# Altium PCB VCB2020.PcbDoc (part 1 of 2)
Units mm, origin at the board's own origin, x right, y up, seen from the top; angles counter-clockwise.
Board outline 146 x 101 mm, 2 copper layers (Top Layer, Bottom Layer); 144 components, 94 nets, 477 pads, 404 vias.
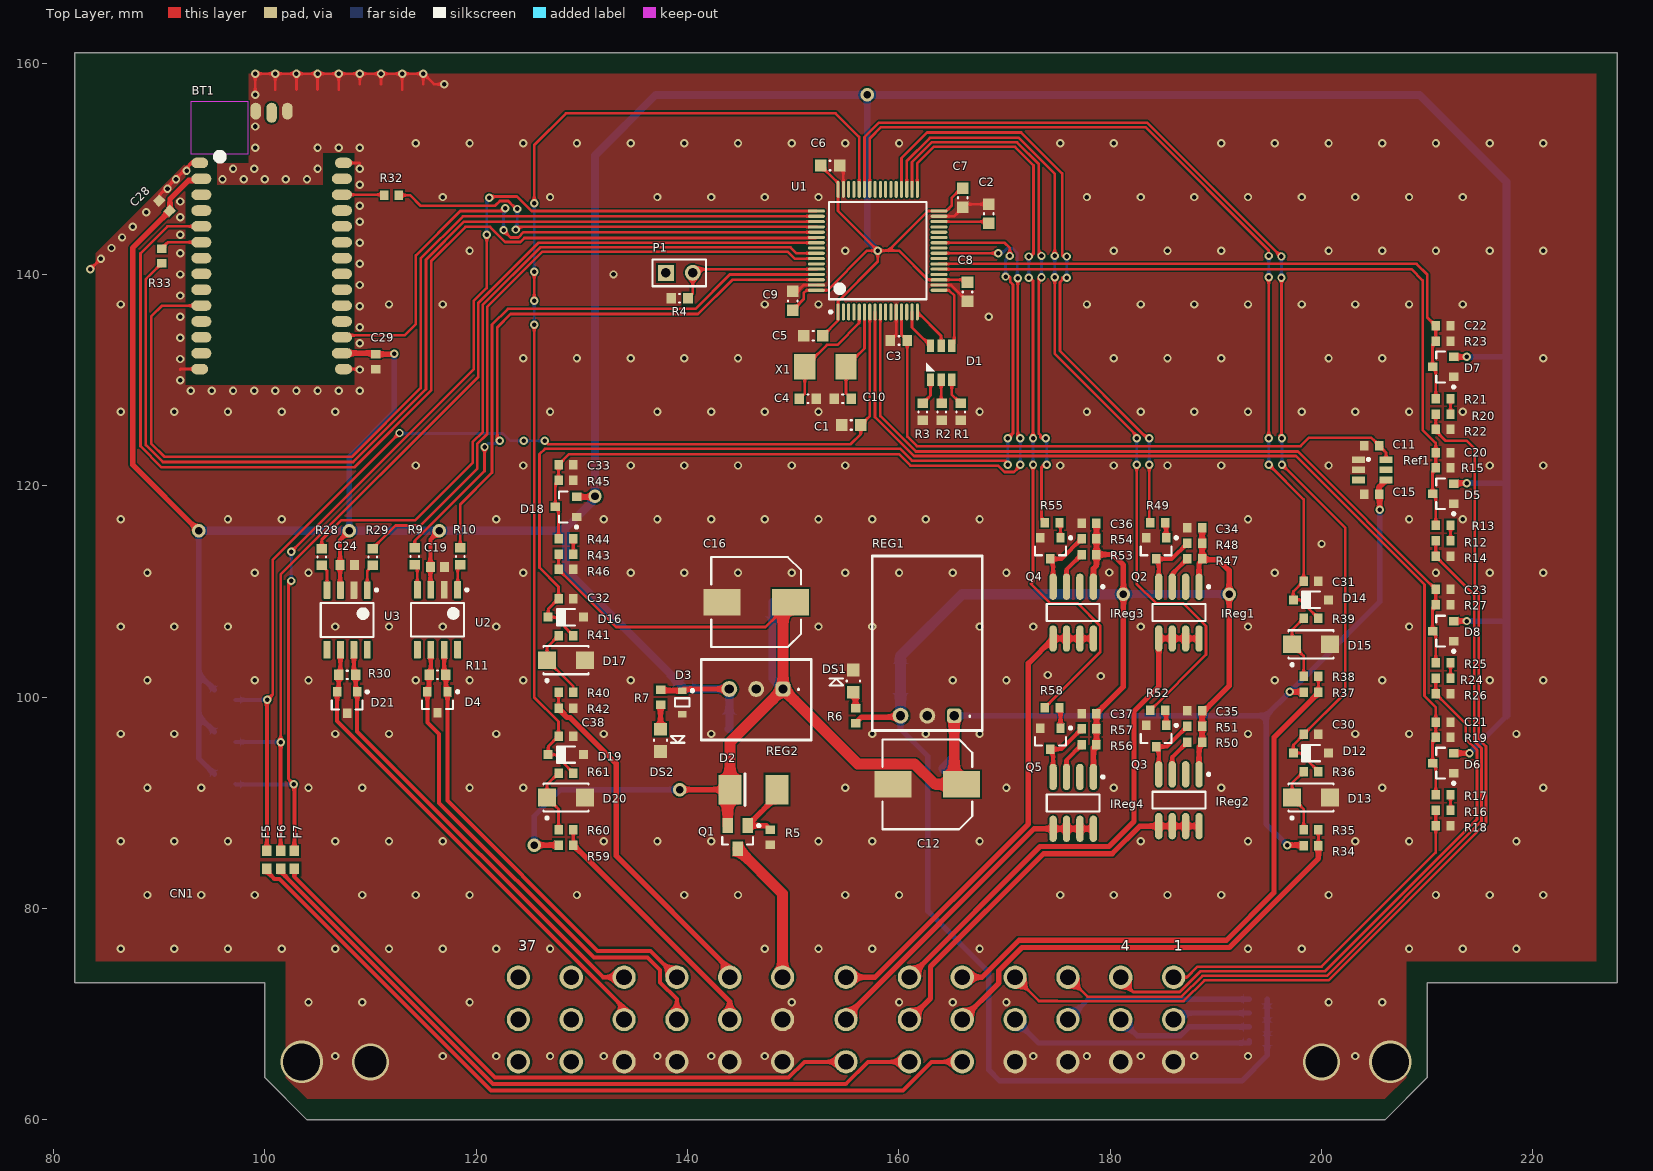
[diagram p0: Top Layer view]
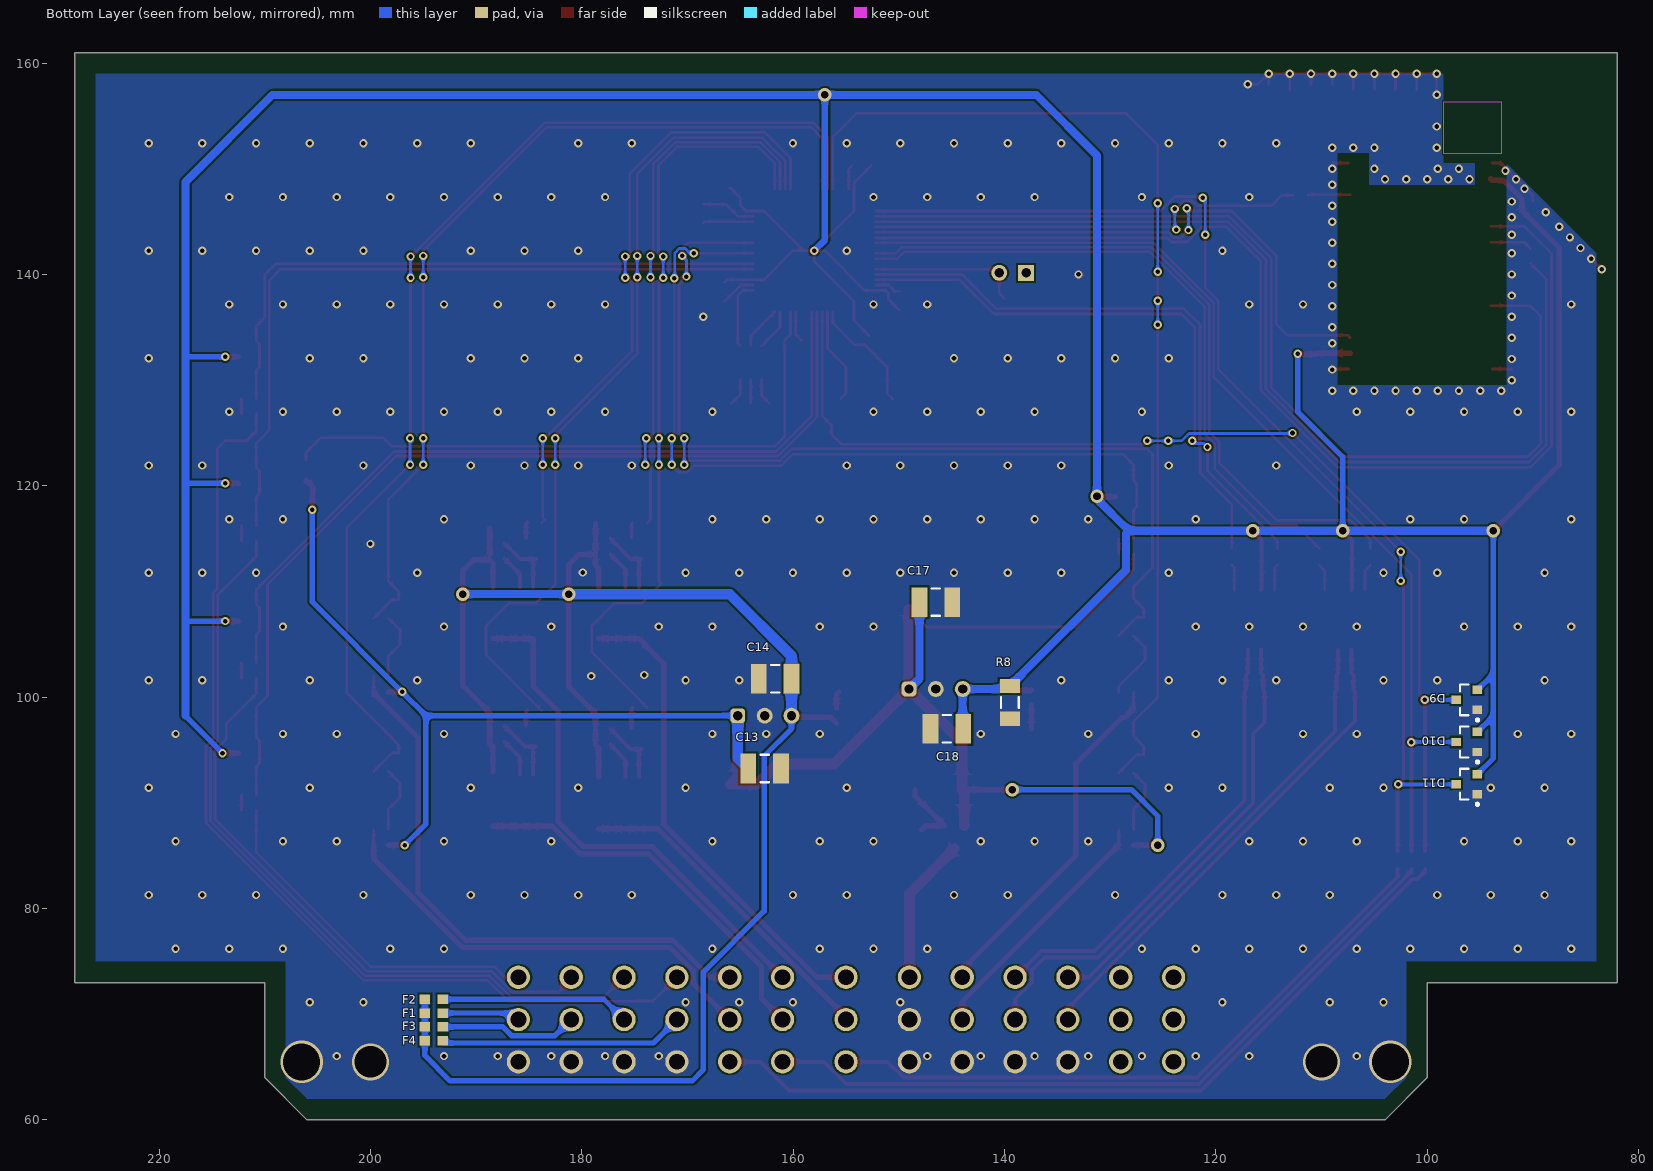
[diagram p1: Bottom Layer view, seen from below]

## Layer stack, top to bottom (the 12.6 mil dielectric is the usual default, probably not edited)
Top Solder: solder mask 0.0102, Solder Resist, Dk 3.5
Top Layer: signal copper 0.0356
Dielectric 1: dielectric 0.32, FR-4, Dk 4.8
Bottom Layer: signal copper 0.0356
Bottom Solder: solder mask 0.0102, Solder Resist, Dk 3.5

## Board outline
210,64 206,60 104,60 100,64 100,73 82,73 82,161 228,161 228,73 210,73

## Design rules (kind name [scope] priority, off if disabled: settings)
Clearance [All] p1: gap=0.178 ignorepadtopadclearanceinfootprint=FALSE except(0: Arc-Hole Track-Hole SMDPad-Hole THPad-Hole Via-Hole Fill-Hole Poly-Hole Region-Hole Text-Hole)
DiffPairsRouting [All] p1: maxlimit=0.254 minlimit=0.254 mostfreqgap=0.254 toplayer_minwidth=0.381 toplayer_maxwidth=0.381 toplayer_prefwidth=0.381 bottomlayer_minwidth=0.381 bottomlayer_maxwidth=0.381 bottomlayer_prefwidth=0.381 maxuncoupledlength=12.7
Height [All] p1: minheight=0 maxheight=1000 prefheight=12.7
HoleSize [All] p1: absolutevalues=TRUE maxlimit=5.08 minlimit=0.381 maxpercent=80.000 minpercent=20.000
HoleToHoleClearance [All] p1: gap=0.203 allowstackedmicrovias=TRUE
MinimumAnnularRing MinimumAnnularRing_Pad [IsPad] p1: minimumring=0.178
MinimumAnnularRing MinimumAnnularRing_Via [IsVia] p2: minimumring=0.127
MinimumSolderMaskSliver [All] p1: minsoldermaskwidth=0.102
PlaneClearance [All] p1: clearance=0.381
PlaneConnect PlaneConnect_12V [InNet('12V')] p1: planeconnectstyle=Direct reliefexpansion=0.508 reliefentries=4 reliefconductorwidth=0.508 reliefairgap=0.254
PlaneConnect PlaneConnect_1 [All] p2: planeconnectstyle=Relief reliefexpansion=0.381 reliefentries=4 reliefconductorwidth=0.381 reliefairgap=0.254
PolygonConnect [All] p1: connectstyle=Direct reliefconductorwidth=0.381 reliefentries=4 polygonreliefangle="90 Angle" airgapwidth=0.254
RoutingVias [All] p1: holewidth=0.432 width=0.787 viastyle="Through Hole" minholewidth=0.381 minwidth=0.737 maxholewidth=1.27 maxwidth=2.54
SilkToSilkClearance [All] p1: silktosilkclearance=0.178
SilkToSolderMaskClearance [IsPad] p1: minsilkscreentomaskgap=0.051 clearancetoexposedcopper=TRUE
SolderMaskExpansion [All] p1: expansion=0.076
Width [All] p1: maxlimit=5.08 minlimit=0.178 preferedwidth=0.381
21 further rules are at their usual default settings.

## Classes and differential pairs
component class 10-DashLEDs: C34 C35 C36 C37 IReg1 IReg2 IReg3 IReg4 Q2 Q3 Q4 Q5 R47 R48 R49 R50 R51 R52 R53 R54 R55 R56 R57 R58
component class 9-Other_Inputs: C30 C31 C32 C33 C38 D12 D13 D14 D15 D16 D17 D18 D19 D20 R34 R35 R36 R37 R38 R39 R40 R41 R42 R43 R44 R45 R46 R59 R60 R61
component class 8-Bluetooth: BT1 C28 C29 R32 R33
component class 5-Connector: CN1 D9 D10 D11 F1 F2 F3 F4 F5 F6 F7
component class 4-PPS: C20 C21 C22 C23 D5 D6 D7 D8 R12 R13 R14 R15 R16 R17 R18 R19 R20 R21 R22 R23 R24 R25 R26 R27
component class 3-CAN: C19 C24 D4 D21 R9 R10 R11 R28 R29 R30 U2 U3
component class 2-Power: C11 C12 C13 C14 C15 C16 C17 C18 D2 D3 DS1 DS2 Q1 R5 R6 R7 R8 Ref1 REG1 REG2
component class 1-Controller: C1 C2 C3 C4 C5 C6 C7 C8 C9 C10 D1 P1 R1 R2 R3 R4 U1 X1
differential pair Sensor_CAN: +Sensor_CAN_P -Sensor_CAN_N
differential pair CAN: +CAN_P -CAN_N

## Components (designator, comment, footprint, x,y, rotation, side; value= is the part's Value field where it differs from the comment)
BT1 "WT12" WT12 100.65,147.95 r270 top
C1 "CAP 10nF 100V 0603(1608)" CAPC0603(1608)100_M 155.5,125.75 r0 top value=10nF
C2 "CAP 4.7uF 10V 0603" CAPC0603(1608)100_M 168.5,145.75 r270 top value=4.7uF
C3 "CAP 100nF 25V 0603(1608)" CAPC0603(1608)100_N 160,133.75 r0 top value=100nF
C4 "CAP 24pF" CAPC0603(1608)100_N 151.396,128.25 r180 top value=24pF
C5 "CAP 10nF 100V 0603(1608)" CAPC0603(1608)100_M 151.9,134.196 r0 top value=10nF
C6 "CAP 10nF 100V 0603(1608)" CAPC0603(1608)100_M 153.5,150.304 r180 top value=10nF
C7 "CAP 10nF 100V 0603(1608)" CAPC0603(1608)100_M 166.054,147.25 r90 top value=10nF
C8 "CAP 10nF 100V 0603(1608)" CAPC0603(1608)100_M 166.5,138.35 r90 top value=10nF
C9 "CAP 10nF 100V 0603(1608)" CAPC0603(1608)100_M 149.946,137.5 r270 top value=10nF
C10 "CAP 24pF" CAPC0603(1608)100_N 154.7,128.25 r0 top value=24pF
C11 "Cap" 1608[0603] 204.75,123.804 r0 top value=1uF
C12 "UUD1H101MNL1GS" NIC-CAPA2-8X10_V 162.7,91.75 r180 top
C13 "Cap" C1210_M 162.7,93.25 r0 bottom value=22uF
C14 "Cap" C1210_M 161.7,101.75 r180 bottom value=10uF
C15 "Cap" 1608[0603] 204.75,119.196 r0 top value=100nF
C16 "UUD1H101MNL1GS" NIC-CAPA2-8X10_V 146.5,109 r180 top
C17 "Cap" C1210_M 146.5,109 r0 bottom value=22uF
C18 "Cap" C1210_M 145.45,97 r180 bottom value=10uF
C19 "0.1uF" CAPC1608X90X30NL10T20 116.345,112.329 r180 top
C20 "Cap" 1608[0603] 211.5,123.144 r180 top value=0.47uF
C21 "Cap" 1608[0603] 211.5,97.644 r180 top value=0.47uF
C22 "Cap" 1608[0603] 211.5,135.144 r180 top value=0.47uF
C23 "Cap" 1608[0603] 211.5,110.204 r180 top value=0.47uF
C24 "0.1uF" CAPC1608X90X30NL10T20 107.8,112.513 r180 top
C28 "Cap" 1608[0603] 90.5,146.5 r315 top value=100nF
C29 "Cap" 1608[0603] 110.5,131.75 r90 top value=100nF
C30 "Cap" 1608[0603] 199,96.471 r180 top value=100nF
C31 "Cap" 1608[0603] 199,110.971 r180 top value=100nF
C32 "Cap" 1608[0603] 128.5,109.321 r180 top value=1nF
C33 "Cap" 1608[0603] 128.5,121.996 r180 top value=0.47uF
C34 "Cap" 1608[0603] 188,116.013 r0 top value=100nF
C35 "Cap" 1608[0603] 188,98.704 r0 top value=100nF
C36 "Cap" 1608[0603] 178,116.454 r0 top value=100nF
C37 "Cap" 1608[0603] 178,98.454 r0 top value=100nF
C38 "Cap" 1608[0603] 128.5,96.321 r180 top value=100nF
CN1 "5-1418363-3" 5-1418363-3 155,69.5 r0 top
D1 "CLX6F-FKC-CNP1ST1E1BB7D3D3" CLX6C-FKB 164,130.05 r90 top
D2 "Zener Diode, 5.1V, 5W SMBJ5338B" "DO-214AA (SMB)" 146.25,91.25 r180 top
D3 "MM3Z3V6T1G" ONSC-SOD-323-2-477-02_V 139.5,99.5 r270 top
D4 "NUP2105LT1" ONSC-SOT-23-3-318-08_V 116.345,99.516 r270 top
D5 "SZNUP1301ML3T1G" ONSC-SOT-23-3-318-08_V 211.5,119.25 r180 top
D6 "SZNUP1301ML3T1G" ONSC-SOT-23-3-318-08_V 211.5,93.75 r180 top
D7 "SZNUP1301ML3T1G" ONSC-SOT-23-3-318-08_V 211.5,131.25 r180 top
D8 "SZNUP1301ML3T1G" ONSC-SOT-23-3-318-08_V 211.5,106.25 r180 top
D9 "SZNUP1301ML3T1G" ONSC-SOT-23-3-318-08_V 96.25,99.75 r0 bottom
D10 "SZNUP1301ML3T1G" ONSC-SOT-23-3-318-08_V 96.25,95.761 r0 bottom
D11 "SZNUP1301ML3T1G" ONSC-SOT-23-3-318-08_V 96.25,91.771 r0 bottom
D12 "MMSZ5226B-E3-08" VISH-SOD-123-2_V 199,94.717 r180 top
D13 "SS14-E3/5AT" VISH-DO-214AC-2_V 199,90.5 r180 top
D14 "MMSZ5226B-E3-08" VISH-SOD-123-2_V 199,109.217 r180 top
D15 "SS14-E3/5AT" VISH-DO-214AC-2_V 199,105 r180 top
D16 "MMSZ5226B-E3-08" VISH-SOD-123-2_V 128.5,107.567 r180 top
D17 "SS14-E3/5AT" VISH-DO-214AC-2_V 128.5,103.5 r180 top
D18 "SZNUP1301ML3T1G" ONSC-SOT-23-3-318-08_V 128.5,118 r180 top
D19 "MMSZ5226B-E3-08" VISH-SOD-123-2_V 128.5,94.567 r180 top
D20 "SS14-E3/5AT" VISH-DO-214AC-2_V 128.5,90.5 r180 top
D21 "NUP2105LT1" ONSC-SOT-23-3-318-08_V 107.8,99.5 r270 top
DS1 "LTST-C170GKT" LTST-C170GKT_V 155.7,101.529 r90 top
DS2 "LTST-C170GKT" LTST-C170GKT_V 137.45,95.916 r270 top
F1 "PTC 80 mA" "0603 fuse" 194,70.113 r180 bottom
F2 "PTC 80 mA" "0603 fuse" 194,71.42 r180 bottom
F3 "PTC 80 mA" "0603 fuse" 194,68.807 r180 bottom
F4 "PTC 80 mA" "0603 fuse" 194,67.5 r180 bottom
F5 "PTC 80 mA" "0603 fuse" 100.193,84.6 r270 top
F6 "PTC 80 mA" "0603 fuse" 101.5,84.6 r270 top
F7 "PTC 80 mA" "0603 fuse" 102.807,84.6 r270 top
IReg1 "NUD4001" SO8_M 186.5,108 r270 top
IReg2 "NUD4001" SO8_M 186.5,90.25 r270 top
IReg3 "NUD4001" SO8_M 176.5,108 r270 top
IReg4 "NUD4001" SO8_M 176.5,90 r270 top
P1 "Header 2" HDR1X2 137.96,140.149 r0 top
Q1 "FDN340P" FAIR-SSOT3L-3_V 144.75,86.75 r270 top
Q2 "MMBT2222ALT1" ONSC-SOT-23-3-318-08_V 184.346,114.079 r270 top
Q3 "MMBT2222ALT1" ONSC-SOT-23-3-318-08_V 184.346,96.329 r270 top
Q4 "MMBT2222ALT1" ONSC-SOT-23-3-318-08_V 174.346,114.079 r270 top
Q5 "MMBT2222ALT1" ONSC-SOT-23-3-318-08_V 174.346,96.079 r270 top
R1 "82R" RESC0603(1608)_N 165.859,127 r270 top value="82.00 Ohm"
R2 "60R" RESC0603(1608)_N 164.054,127 r270 top value="60.40 Ohm"
R3 "33R" RESC0603(1608)_N 162.25,127 r270 top value="33.00 Ohm"
R4 "10K" RESC0603(1608)_N 139.25,137.75 r180 top value="10000.00 Ohm"
R5 "Res1" 1608[0603] 147.854,86.75 r90 top value=1K
R6 "Res1" 1608[0603] 155.904,98.25 r90 top value=180R
R7 "Res1" 1608[0603] 137.45,100 r270 top value=82R
R8 "100R" RESC1206(3216)_M 139.5,99.5 r90 bottom value="100.00 Ohm"
R9 "22R" RESC0603(1608)_N 114.191,113.321 r90 top value="22.00 Ohm"
R10 "22R" RESC0603(1608)_N 118.499,113.321 r90 top value="22.00 Ohm"
R11 "120R" RESC0603(1608)_N 116.345,102.121 r0 top value="120.00 Ohm"
R12 "Res1" 1608[0603] 211.5,114.791 r0 top value=3k9
R13 "Res1" 1608[0603] 211.5,116.246 r180 top value=1k3
R14 "Res1" 1608[0603] 211.5,113.337 r180 top value=10k
R15 "Res1" 1608[0603] 211.5,121.689 r180 top value=10k
R16 "Res1" 1608[0603] 211.5,89.291 r0 top value=3k9
R17 "Res1" 1608[0603] 211.5,90.746 r180 top value=1k3
R18 "Res1" 1608[0603] 211.5,87.837 r180 top value=10k
R19 "Res1" 1608[0603] 211.5,96.189 r180 top value=10k
R20 "Res1" 1608[0603] 211.5,126.791 r0 top value=3k9
R21 "Res1" 1608[0603] 211.5,128.246 r180 top value=1k3
R22 "Res1" 1608[0603] 211.5,125.337 r180 top value=10k
R23 "Res1" 1608[0603] 211.5,133.689 r180 top value=10k
R24 "Res1" 1608[0603] 211.5,101.791 r0 top value=3k9
R25 "Res1" 1608[0603] 211.5,103.246 r180 top value=1k3
R26 "Res1" 1608[0603] 211.5,100.337 r180 top value=10k
R27 "Res1" 1608[0603] 211.5,108.75 r180 top value=10k
R28 "22R" RESC0603(1608)_N 105.396,113.263 r90 top value="22.00 Ohm"
R29 "22R" RESC0603(1608)_N 110.204,113.263 r90 top value="22.00 Ohm"
R30 "120R" RESC0603(1608)_N 107.8,102.104 r0 top value="120.00 Ohm"
R32 "Res1" 1608[0603] 112,147.5 r0 top value=22R
R33 "Res1" 1608[0603] 90.25,141.75 r90 top value=22R
R34 "Res1" 1608[0603] 199,85.963 r180 top value=10k
R35 "Res1" 1608[0603] 199,87.463 r180 top value=5k1
R36 "Res1" 1608[0603] 199,92.963 r0 top value=5k1
R37 "Res1" 1608[0603] 199,100.463 r180 top value=10k
R38 "Res1" 1608[0603] 199,101.963 r180 top value=5k1
R39 "Res1" 1608[0603] 199,107.463 r0 top value=5k1
R40 "Res1" 1608[0603] 128.5,100.463 r180 top value=1K
R41 "Res1" 1608[0603] 128.5,105.812 r180 top value=1K
R42 "Res1" 1608[0603] 128.5,98.963 r180 top value=1K
R43 "Res1" 1608[0603] 128.5,113.541 r0 top value=39k
R44 "Res1" 1608[0603] 128.5,114.996 r180 top value=2k
R45 "Res1" 1608[0603] 128.5,120.541 r180 top value=10k
R46 "Res1" 1608[0603] 128.5,112.087 r180 top value=10k
R47 "Res1" 1608[0603] 188,113.104 r180 top value=3R
R48 "Res1" 1608[0603] 188,114.559 r180 top value=110k
R49 "Res1" 1608[0603] 184.5,116.509 r180 top value=1K
R50 "Res1" 1608[0603] 188,95.75 r180 top value=3R
R51 "Res1" 1608[0603] 188,97.25 r180 top value=110k
R52 "Res1" 1608[0603] 184.5,98.759 r180 top value=1K
R53 "Res1" 1608[0603] 178,113.5 r180 top value=3R
R54 "Res1" 1608[0603] 178,115 r180 top value=110k
R55 "Res1" 1608[0603] 174.5,116.509 r180 top value=1K
R56 "Res1" 1608[0603] 178,95.5 r180 top value=3R
R57 "Res1" 1608[0603] 178,97 r180 top value=110k
R58 "Res1" 1608[0603] 174.5,99 r180 top value=1K
R59 "Res1" 1608[0603] 128.5,86.008 r180 top value=10k
R60 "Res1" 1608[0603] 128.5,87.463 r180 top value=5k1
R61 "Res1" 1608[0603] 128.5,92.812 r0 top value=5k1
Ref1 "LT6654AHS6-3.3" "TSOT-23 S6" 204.75,121.5 r0 top
REG1 "OKI-78SR-5" "Reg - TH, 3 pin, 100 mil Pitch, HTL" 162.7,96.98 r180 top
REG2 "OKI-78SR-3.3" "Reg - TH, 3 pin, 100 mil Pitch, VTL" 146.5,99.5 r180 top
U1 "STM32F446RCT7TR" STM-LQFP64_L 158,142.25 r90 top
U2 "SN65HVD232DR" D0008A_M 116.345,107.325 r270 top
U3 "SN65HVD232DR" D0008A_M 107.8,107.309 r270 top
X1 "7A-8.000MAAJ-T" "2-SMD, No Lead" 153,131.25 r180 top

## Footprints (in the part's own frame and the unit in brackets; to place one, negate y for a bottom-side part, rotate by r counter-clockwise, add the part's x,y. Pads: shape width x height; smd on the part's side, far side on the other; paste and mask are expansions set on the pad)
"2-SMD, No Lead" [mm]
  rect 2x2.4 smd: 1(-2,0) 2(1.9,0)
  body extent -2.5,-1.6 2.5,1.6, height 1.2
5-1418363-3 [mm] "Levyseal 90 degree 39 pin header"
  round 2.2 hole 1.5: 1(31,4) 2(31,0) 3(31,-4) 4(26,4) 5(26,0) 6(26,-4) 7(21,4) 8(21,0) 9(21,-4) 10(16,4) 11(16,0) 12(16,-4) 13(11,4) 14(11,0) 15(11,-4) 16(6,4) 17(6,0) 18(6,-4) 19(0,4) 20(0,0) 21(0,-4) 22(-6,4) 23(-6,0) 24(-6,-4) 25(-11,4) 26(-11,0) 27(-11,-4) 28(-16,4) 29(-16,0) 30(-16,-4) 31(-21,4) 32(-21,0) 33(-21,-4) 34(-26,4) 35(-26,0) 36(-26,-4) 37(-31,4) 38(-31,0) 39(-31,-4)
  body extent -66,-47.4 66,10.4, height 37
"0603 fuse" [mm] "0603 PTC fuse"
  rect 1x0.9 smd: 1(-0.85,0) 2(0.85,0)
  body extent -1,-0.41 1,0.41, height 0.7
1608[0603] [mm] "Chip Capacitor, Body 1.6x0.8mm, IPC High Density"
  rect 0.8x0.9 smd: 1(-0.7,0) 2(0.7,0)
  body extent -0.87,-0.48 0.87,0.48, height 1.3
C1210_M [mm] "Chip Capacitor, Body 3.2x2.5mm, IPC Low Density"
  rect 1.5x2.8 smd: 1(-1.55,0) 2(1.55,0)
  silkscreen extent -0.4,-1.3 0.4,1.3, body extent -1.7,-1.35 1.7,1.35, height 1.5
CAPC0603(1608)100_M [mm] "Chip Capacitor, Body 1.6x0.8mm, Height 1.0mm, IPC Low Density"
  rect 1.1x1.1 smd: 1(-0.9,0) 2(0.9,0)
  silkscreen extent -0.05,-0.45 0.05,0.45, body extent -0.87,-0.47 0.88,0.48, height 1
CAPC0603(1608)100_N [mm] "Chip Capacitor, Body 1.6x0.8mm, Height 1.0mm, IPC Medium Density"
  rect 0.9x1 smd: 1(-0.8,0) 2(0.8,0)
  silkscreen extent -0.05,-0.4 0.05,0.4, body extent -0.87,-0.48 0.88,0.47, height 1
CAPC1608X90X30NL10T20 [mm] "Chip Capacitor, 2-Leads, Body 1.70x0.90mm, IPC Medium Density"
  rect 0.85x0.95 smd: 1(-0.675,0) 2(0.675,0)
  body extent -0.85,-0.45 0.85,0.45, height 0.9
CLX6C-FKB [mm] "6-SMD, J-Lead, 1mm"
  rect 1.2x0.7 smd: 1(0,1) 2(0,0) 3(0,-1) 4(3.2,-1) 5(3.2,0) 6(3.2,1)
  silkscreen extent 0.8,0.6 1.6,1.4, body extent -0.1,-1.7 3.3,1.7, height 1
D0008A_M [mm] "SOIC, 8-Leads, Body 5x4mm, Pitch 1.27mm, IPC Low Density"
  rrect15% 1.65x0.65 smd: 1(-2.825,1.905) 2(-2.825,0.635) 3(-2.825,-0.635) 4(-2.825,-1.905) 5(2.825,-1.905) 6(2.825,-0.635) 7(2.825,0.635) 8(2.825,1.905)
  silkscreen extent -2.95,-2.5 1.6,2.91, body extent -3,-2.45 3,2.45, height 1.63
"DO-214AA (SMB)" [mm]
  rect 2.16x2.8 smd: A(-2.225,0) K(2.225,0)
  silkscreen extent 0.8,-1.5 0.8,1.5, body extent -2.87,-1.95 2.88,1.95, height 2.41
FAIR-SSOT3L-3_V [mm] "SOT23, 3-Leads, Body 2.92x1.4mm, Pitch 0.95mm"
  rect 1.4x1 smd: 1(-1.1,0.95) 2(-1.1,-0.95) 3(1.1,0)
  silkscreen extent -1.22,-1.46 0.7,2.13, body extent -1.26,-1.46 1.26,1.46, height 1.12
HDR1X2 [mm] "Connector; Header; 2 Position"
  rect 1.5x1.5 hole 0.9: 1(0,0)
  round 1.5 hole 0.9: 2(2.54,0)
  silkscreen extent -1.27,-1.27 3.81,1.27
LTST-C170GKT_V [mm] "SMD, 2-Leads, Body 2x1.25mm"
  rect 1.2x1.2 smd: 1(-1.05,0) 2(1.05,0)
  silkscreen extent -0.41,-0.63 0.23,2.25, body extent -1,-0.63 1,0.63, height 1.1
NIC-CAPA2-8X10_V [mm] "Aluminum Electrolytic Capacitor, Diameter 8mm, Height 10.8mm, Pitch 6.5mm"
  rect 3.5x2.5 smd: 1(-3.25,0) 2(3.25,0)
  silkscreen extent -4.25,-4.25 4.25,4.25, body extent -3.99,-3.97 3.99,4, height 10.8
ONSC-SOD-323-2-477-02_V [mm] "SOD, 2-Leads, Body 1.7x1.25mm"
  rect 0.63x0.83 smd: 1(-1.115,0) 2(1.115,0)
  silkscreen extent -1.24,-0.67 0.4,1.09, body extent -0.85,-0.63 0.85,0.63, height 1.06
ONSC-SOT-23-3-318-08_V [mm] "SOT23, 3-Leads, Body 2.92x1.3mm, Pitch 0.95mm"
  rect 0.9x0.8 smd: 1(-1,0.95) 2(-1,-0.95) 3(1,0)
  silkscreen extent -1.12,-1.46 0.65,2.03, body extent -0.65,-1.46 0.65,1.46, height 1.11
"Reg - TH, 3 pin, 100 mil Pitch, HTL" [mm] "OKI-78SR"
  rrect50% 1.4x1.4 hole 0.889: 1(-2.54,-1.27)
  round 1.5 hole 0.889: 2(0,-1.27) 3(2.54,-1.27)
  silkscreen extent -5.21,-16.38 5.21,0.13, body extent -5.28,-16.46 5.13,0.05, height 7.67
"Reg - TH, 3 pin, 100 mil Pitch, VTL" [mm] "OKI-78SR"
  rrect50% 1.4x1.4 hole 0.889: 1(-2.54,-1.27)
  round 1.5 hole 0.889: 2(0,-1.27) 3(2.54,-1.27)
  silkscreen extent -5.21,-4.06 5.21,3.56, body extent -5.21,-4.05 5.21,3.68, height 16.51
RESC0603(1608)_N [mm] "Chip Resistor, Body 1.6x0.8mm, IPC Medium Density"
  rect 0.9x1 smd: 1(-0.8,0) 2(0.8,0)
  silkscreen extent -0.05,-0.4 0.05,0.4, body extent -0.85,-0.47 0.85,0.47, height 0.6
RESC1206(3216)_M [mm] "Chip Resistor, Body 3.2x1.6mm, IPC Low Density"
  rect 1.35x1.9 smd: 1(-1.55,0) 2(1.55,0)
  silkscreen extent -0.5,-0.85 0.5,0.85, body extent -1.67,-0.87 1.67,0.87, height 0.75
SO8_M [mm] "SOIC, 8-Leads, Body 4.9x3.9mm, Pitch 1.27mm, IPC Low Density"
  oval 2.5x0.7 smd: 1(-2.45,1.905) 2(-2.45,0.635) 3(-2.45,-0.635) 4(-2.45,-1.905) 5(2.45,-1.905) 6(2.45,-0.635) 7(2.45,0.635) 8(2.45,1.905)
  silkscreen extent -2.57,-2.5 0.8,2.93, body extent -2,-2.5 2,2.5, height 1.75
STM-LQFP64_L [mm] "QFP, 64-Leads, Body 10x10mm, Pitch 0.5mm, IPC High Density"
  oval 1.6x0.3 smd: 1(-5.8,3.75) 2(-5.8,3.25) 3(-5.8,2.75) 4(-5.8,2.25) 5(-5.8,1.75) 6(-5.8,1.25) 7(-5.8,0.75) 8(-5.8,0.25) 9(-5.8,-0.25) 10(-5.8,-0.75) 11(-5.8,-1.25) 12(-5.8,-1.75) 13(-5.8,-2.25) 14(-5.8,-2.75) 15(-5.8,-3.25) 16(-5.8,-3.75) 33(5.8,-3.75) 34(5.8,-3.25) 35(5.8,-2.75) 36(5.8,-2.25) 37(5.8,-1.75) 38(5.8,-1.25) 39(5.8,-0.75) 40(5.8,-0.25) 41(5.8,0.25) 42(5.8,0.75) 43(5.8,1.25) 44(5.8,1.75) 45(5.8,2.25) 46(5.8,2.75) 47(5.8,3.25) 48(5.8,3.75)
  oval 0.3x1.6 smd: 17(-3.75,-5.8) 18(-3.25,-5.8) 19(-2.75,-5.8) 20(-2.25,-5.8) 21(-1.75,-5.8) 22(-1.25,-5.8) 23(-0.75,-5.8) 24(-0.25,-5.8) 25(0.25,-5.8) 26(0.75,-5.8) 27(1.25,-5.8) 28(1.75,-5.8) 29(2.25,-5.8) 30(2.75,-5.8) 31(3.25,-5.8) 32(3.75,-5.8) 49(3.75,5.8) 50(3.25,5.8) 51(2.75,5.8) 52(2.25,5.8) 53(1.75,5.8) 54(1.25,5.8) 55(0.75,5.8) 56(0.25,5.8) 57(-0.25,5.8) 58(-0.75,5.8) 59(-1.25,5.8) 60(-1.75,5.8) 61(-2.25,5.8) 62(-2.75,5.8) 63(-3.25,5.8) 64(-3.75,5.8)
  silkscreen extent -5.92,-4.6 4.6,4.6, body extent -5,-5 5,5, height 1.6
"TSOT-23 S6" [mm]
  rect 1.22x0.62 smd: 1(-1.27,0.95) 2(-1.27,0) 3(-1.27,-0.95) 4(1.35,-0.95) 5(1.35,0) 6(1.35,0.95)
  silkscreen extent -0.43,0.9 -0.21,1.12, body extent -0.85,-1.45 0.89,1.45, height 1
VISH-DO-214AC-2_V [mm] "SMA, 2-Leads, Body 4.245x2.665mm, Height 2.29mm"
  rect 1.7x1.68 smd: 1(-1.79,0) 2(1.79,0)
  silkscreen extent -2.12,-1.33 2.12,2.06, body extent -2.57,-1.33 2.57,1.33, height 2.29
VISH-SOD-123-2_V [mm] "SMD, 2-Leads, Body 2.7x1.55mm, Height 1.35mm"
  rect 0.85x0.85 smd: 1(-1.675,0) 2(1.675,0)
  silkscreen extent -0.85,-0.77 0.85,0.78, body extent -1.35,-0.77 1.35,0.77, height 1.35
WT12 [mm] "Bluegiga WT12 Bluetooth Module"
  rrect100% 1x1.6 smd: 1(-2.6,-6.8) 14(16.9,-6.8) 15(16.9,6.8) 28(-2.6,6.8)
  rrect100% 1x1.9 smd: 2(-1.1,-6.65) 3(0.4,-6.65) 4(1.9,-6.65) 5(3.4,-6.65) 6(4.9,-6.65) 7(6.4,-6.65) 8(7.9,-6.65) 9(9.4,-6.65) 10(10.9,-6.65) 11(12.4,-6.65) 12(13.9,-6.65) 13(15.4,-6.65) 16(15.4,6.65) 17(13.9,6.65) 18(12.4,6.65) 19(10.9,6.65) 20(9.4,6.65) 21(7.9,6.65) 22(6.4,6.65) 23(4.9,6.65) 24(3.4,6.65) 25(1.9,6.65) 26(0.4,6.65) 27(-1.1,6.65)
  rrect100% 1.6x1 smd: 29(-7.5,1.5) 31(-7.5,-1.5)
  rrect100% 1.9x1 smd: 30(-7.35,0)
  Keep-Out Layer region: -8.4,-7.65 -3.45,-7.65 -3.45,-2.2 -8.4,-2.2
  silkscreen extent -3.33,-5.04 -3.05,-4.76, body extent -7.7,-7 17.9,7, height 2.5

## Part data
C1 C5 C6 C7 C8 C9: library part CMP-1035-02326-1, "CAP 10nF 100V ±20% 0603 (1608 Metric) Thickness 1mm SMD", Case-EIA=0603, Case-Metric=1608, Rated Voltage="100 V", Tolerance=±20%
C2: library part CMP-1035-02787-1, "CAP 4.7uF 10V ±20% 0603 (1608 Metric) Thickness 1mm SMD", Case-EIA=0603, Case-Metric=1608, Rated Voltage="10 V", Tolerance=±20%
C3: library part CMP-1035-02589-1, "CAP 100nF 25V ±20% 0603 (1608 Metric) Thickness 1mm SMD", Case-EIA=0603, Case-Metric=1608, Rated Voltage="25 V", Tolerance=±20%
C4 C10: library part CMP-1035-00843-1, "CAP 24pF 16V ±2% 0603 (1608 Metric) Thickness 1mm SMD", Case-EIA=0603, Case-Metric=1608, Rated Voltage="16 V", Tolerance=±2%
C11: "Capacitor", Capacitance=1µF, Manufacturer="Murata Electronics North America", Manufacturer Part Number=GRM188R61E105KA12D, Operating Temperature="-55°C ~ 85°C", Package / Case="0603 (1608 Metric)", Ratings=-, Supplier Part Number 1=490-3897-1-ND, Temperature Coefficient=X5R, Tolerance=±10%, Voltage - Rated=25V
C12 C16: library part CMP-0687-00073-1, "Aluminum Electrolytic Capacitor, UD Series, Low Impedance, 100 uF, 50 V, + / - 20%, -55 to 105 degC, Chip Type, 8 x 10 mm D x L, Pb-Free, Reel", Capacitance=100µF, ESR (Equivalent Series Resistance)=-, Lifetime @ Temp.="5000 Hrs @ 105°C", Manufacturer=Nichicon, Operating Temperature="-55°C ~ 105°C", Package / Case="Radial, Can - SMD", Rated Capacitance="100 uF", Rated Ripple Current (at 100kHz)="300 mA", Rated Voltage="50 V", Ripple Current=300mA, Supplier Part Number 1=493-2306-1-ND, Tolerance=±20%, Tolerance Rated Capacitance="-20 to 20%", Voltage Rating=50V
C13 C17: "Capacitor", Capacitance=22µF, Manufacturer=Yageo, Manufacturer Part Number=CC1210MKX5R8BB226, Operating Temperature="-55°C ~ 85°C", Package / Case="1210 (3225 Metric)", Ratings=-, Supplier Part Number 1=311-2056-1-ND, Temperature Coefficient=X5R, Tolerance=±20%, Voltage - Rated=25V
C14 C18: "Capacitor", Capacitance=10µF, Manufacturer=Yageo, Manufacturer Part Number=CC1210ZKY5V8BB106, Operating Temperature="-30°C ~ 85°C", Package / Case="1210 (3225 Metric)", Ratings=-, Supplier Part Number 1=311-2063-1-ND, Temperature Coefficient="Y5V (F)", Tolerance="-20%, +80%", Voltage - Rated=25V
C15 C28 C29 C30 C31 C34 C35 C36 C37 C38: "Capacitor", Capacitance=0.10µF, Manufacturer=Yageo, Manufacturer Part Number=CC0603KRX7R9BB104, Operating Temperature="-55°C ~ 125°C", Package / Case="0603 (1608 Metric)", Ratings=-, Supplier Part Number 1=311-1344-1-ND, Temperature Coefficient=X7R, Tolerance=±10%, Voltage - Rated=50V
C19 C24: library part CMP-2000-06092-1, "Chip Capacitor, 100 nF, +/- 10%, 50 V, -55 to 125 degC, 0603 (1608 Metric), RoHS, Tape and Reel", Dielectric=X7R, Manufacturer=SamsungElectro-Mechanics, Operating Temperature=-55to125°C, Package/Case=0603, Package Description="2-Pin Surface Mount Device, Body 1.60 x 0.80 mm", Tolerance=10%, Voltage=50Vdc
C20 C21 C22 C23 C33: "Capacitor", Capacitance=0.47µF, Manufacturer=Yageo, Manufacturer Part Number=CC0603KRX7R8BB474, Operating Temperature="-55°C ~ 125°C", Package / Case="0603 (1608 Metric)", Ratings=-, Supplier Part Number 1=311-1805-1-ND, Temperature Coefficient=X7R, Tolerance=±10%, Voltage - Rated=25V
C32: "Capacitor", Capacitance=1000pF, Manufacturer=Yageo, Manufacturer Part Number=CC0603KRX7R9BB102, Operating Temperature="-55°C ~ 125°C", Package / Case="0603 (1608 Metric)", Ratings=-, Supplier Part Number 1=311-1080-1-ND, Temperature Coefficient=X7R, Tolerance=±10%, Voltage - Rated=50V
CN1: "Levyseal 90 degree 39 pin header"
D1: library part "LED - CLX6F-FKC-CNP1ST1E1BB7D3D3", "Red, Green, Blue (RGB) 622nm Red, 530nm Green, 470nm Blue LED Indication - Discrete 2.1V Red, 2.7V Green, 3V Blue 6-SMD, J-Lead"
D2: Part Number=SMBJ5338B, Power=5W, Reverse Voltage=5.1V
D3: library part CMP-1060-00650-1, "Zener Voltage Regulator, 300 mW, 2-Pin SOD-323, Pb-Free, Tape and Reel", Manufacturer="On Semiconductor"
D4 D21: library part CMP-1063-00165-1, "Dual Line CAN Bus Protector, 3-Pin SOT-23, Tape and Reel", Manufacturer="On Semiconductor"
D5 D6 D7 D8 D9 D10 D11 D18: library part CMP-1063-00171-1, "Low Capacitance Diode Array for ESD Protection in a Single Data Line, 3-Pin SOT-23, Pb-Free, Tape and Reel", Manufacturer="On Semiconductor", Supplier Part Number 1=863-SZNUP1301ML3T1G
D12 D14 D16 D19: library part CMP-0931-00026-1, "Small Signal Zener Diode, 3.3 V +/- 5%, -55 to 155 degC, 2-Pin SOD-123, RoHS, Tape and Reel", Current - Reverse Leakage @ Vr="25µA @ 1V", Manufacturer="Vishay Semiconductor", Manufacturer Part Number=MMSZ5226B-7-F, Operating Temperature="-55 to 150 degC", Package / Case=SOD-123, Power - Max=500mW, Power Dissipation (mW)=500, Supplier Part Number 1=MMSZ5226B-FDICT-ND, Test Current (IZT1) (mA)=20, Tolerance="+/- 5%", Voltage - Forward (Vf) (Max) @ If="900mV @ 10mA", Voltage - Zener (Nom) (Vz)=3.3V, Zener Voltage (NOM.) (V)=3.3
D13 D15 D17 D20: library part CMP-0549-00004-1, "Schottky Barrier Rectifier, 40 V Maximum DC Blocking Voltage, -65 to 125 degC, 2-Pin SMA Case, RoHS", Manufacturer="Vishay Semiconductor", Operating Temperature="-65 to 125 degC", Supplier Part Number 1=SS14CT-ND
DS1 DS2: library part CMP-1674-00002-5, "LED Uni-Color Green, 100 mW, 120 mA, -55 to 85 degC, 2-Pin SMD, RoHS, Tape and Reel", Color=Green, Current - Test=10mA, Lens Color=Colorless, Manufacturer=Lite-On, Max Operating Temperature="85 degC", Millicandela Rating=6mcd, Min Operating Temperature="-55 degC", Package / Case="0805 (2012 Metric)", Package Quantity=1, Supplier Device Package=-, Supplier Part Number 1=160-1179-1-ND, Voltage - Forward (Vf) (Typ)=2.1V
F1 F2 F3 F4 F5 F6 F7: library part "PTC fuse 80mA 0ZCM0008FF2G", "0ZCM0008FF2G", Supplier Part Number 1=507-1817-1-ND
IReg1 IReg2 IReg3 IReg4: library part "LED Currnet Driver, 500mA, 30V max", Current - Output / Channel=500mA, Frequency=-, Manufacturer="ON Semiconductor", Manufacturer Part Number=NUD4001DR2G, Operating Temperature="-40°C ~ 125°C (TA)", Package / Case="8-SOIC (0.154\", 3.90mm Width)", Supplier Device Package=8-SOIC, Supplier Part Number 1=NUD4001DR2GOSCT-ND, Voltage - Output=28V, Voltage - Supply (Max)=30V, Voltage - Supply (Min)=3.6V
P1: "Header, 2-Pin"
Q1: library part CMP-2100-03638-1, "Single P-Channel, Logic Level, PowerTrench(R) MOSFET, 2 A, 20 V, -55 to 150 degC, 3-Pin SOT-23, RoHS, Tape and Reel", Case/Package=SOT-23, Continuous Drain Current (ID)=2A, Current Rating=-2A, Drain to Source Breakdown Voltage=-20V, Drain to Source Resistance=60mOhm, Drain to Source Voltage (Vdss)=20V, Gate to Source Voltage (Vgs)=8V, Input Capacitance=779pF, Manufacturer="Fairchild Semiconductor", Max Operating Temperature=150degC, Max Power Dissipation=500mW, Min Operating Temperature=-55degC, Package Description="3-Pin Small Outline Transistor, Body 2.92 x 1.4 mm, Pitch 0.95 mm", Package Quantity=1, Package Reference=SSOT3L, Package Version="Rev. 3, 05/2015", Threshold Voltage=-800mV
Q2 Q3 Q4 Q5: library part CMP-1048-00593-1, "General Purpose Transistor, NPN Silicon, 3-Pin SOT-23, Tape and Reel", Manufacturer="On Semiconductor"
R1: library part CMP-1012-00048-1, "82R 0.1W 5% 0603 (1608 Metric)  SMD", Case-EIA=0603, Case-Metric=1608, Power="0.1 W", Tolerance="5 %"
R2: library part CMP-1012-00372-1, "60R4 0.1W 1% 0603 (1608 Metric)  SMD", Case-EIA=0603, Case-Metric=1608, Power="0.1 W", Tolerance="1 %"
R3: library part CMP-1012-00038-1, "33R 0.1W 5% 0603 (1608 Metric)  SMD", Case-EIA=0603, Case-Metric=1608, Power="0.1 W", Tolerance="5 %"
R4: library part CMP-1012-00098-1, "10K 0.1W 5% 0603 (1608 Metric)  SMD", Case-EIA=0603, Case-Metric=1608, Power="0.1 W", Tolerance="5 %"
R5 R40 R41 R42 R49 R52 R55 R58: "Resistor", Manufacturer="Panasonic Electronic Components", Manufacturer Part Number=ERJ-PA3F1001V, Operating Temperature="-55°C ~ 155°C", Package / Case="0603 (1608 Metric)", Power (Watts)="0.25W, 1/4W", Resistance (Ohms)=1k, Supplier Device Package=0603, Supplier Part Number 1=P1.0KBYCT-ND, Temperature Coefficient=±100ppm/°C, Tolerance=±1%
R6: "Resistor", Manufacturer=Yageo, Manufacturer Part Number=RC0603JR-07180RL, Operating Temperature="-55°C ~ 155°C", Package / Case="0603 (1608 Metric)", Power (Watts)="0.1W, 1/10W", Resistance (Ohms)=180, Supplier Device Package=0603, Supplier Part Number 1=311-180GRCT-ND, Temperature Coefficient=±100ppm/°C, Tolerance=±5%
R7: "Resistor", Manufacturer=Yageo, Manufacturer Part Number=RC0603JR-0782RL, Operating Temperature="-55°C ~ 155°C", Package / Case="0603 (1608 Metric)", Power (Watts)="0.1W, 1/10W", Resistance (Ohms)=82, Supplier Device Package=0603, Supplier Part Number 1=311-82GRCT-ND, Temperature Coefficient=±100ppm/°C, Tolerance=±5%
R8: library part CMP-1014-00050-1, "100R 0.25W 5% 1206 (3216 Metric)  SMD", Case-EIA=1206, Case-Metric=3216, Power="0.25 W", Tolerance="5 %"
R9 R10 R28 R29: library part CMP-1012-00034-1, "22R 0.1W 5% 0603 (1608 Metric)  SMD", Case-EIA=0603, Case-Metric=1608, Power="0.1 W", Tolerance="5 %"
R11 R30: library part CMP-1012-00052-1, "120R 0.1W 5% 0603 (1608 Metric)  SMD", Case-EIA=0603, Case-Metric=1608, Power="0.1 W", Tolerance="5 %"
R12 R16 R20 R24: "Resistor", Manufacturer=Yageo, Manufacturer Part Number=RT0603BRD073K9L, Operating Temperature="-55°C ~ 155°C", Package / Case="0603 (1608 Metric)", Power (Watts)="0.1W, 1/10W", Resistance (Ohms)=3.9k, Supplier Device Package=0603, Supplier Part Number 1=YAG1656CT-ND, Temperature Coefficient=±25ppm/°C, Tolerance=±0.1%
R13 R17 R21 R25: "Resistor", Manufacturer=Yageo, Manufacturer Part Number=RT0603BRD071K3L, Operating Temperature="-55°C ~ 155°C", Package / Case="0603 (1608 Metric)", Power (Watts)="0.1W, 1/10W", Resistance (Ohms)=1.3k, Supplier Device Package=0603, Supplier Part Number 1=YAG1565CT-ND, Temperature Coefficient=±25ppm/°C, Tolerance=±0.1%
R14 R18 R22 R26 R34 R37 R46 R59: "Resistor", Manufacturer=Yageo, Manufacturer Part Number=RC0603JR-0710KL, Operating Temperature="-55°C ~ 155°C", Package / Case="0603 (1608 Metric)", Power (Watts)="0.1W, 1/10W", Resistance (Ohms)=10k, Supplier Device Package=0603, Supplier Part Number 1=311-10KGRCT-ND, Temperature Coefficient=±100ppm/°C, Tolerance=±5%
R15 R19 R23 R27 R45: "Resistor", Manufacturer=Yageo, Manufacturer Part Number=RT0603BRD0710KL, Operating Temperature="-55°C ~ 155°C", Package / Case="0603 (1608 Metric)", Power (Watts)="0.1W, 1/10W", Resistance (Ohms)=10k, Supplier Device Package=0603, Supplier Part Number 1=YAG1236CT-ND, Temperature Coefficient=±25ppm/°C, Tolerance=±0.1%
R32 R33: "Resistor", Manufacturer=Yageo, Manufacturer Part Number=RC0603JR-0722RL, Operating Temperature="-55°C ~ 155°C", Package / Case="0603 (1608 Metric)", Power (Watts)="0.1W, 1/10W", Resistance (Ohms)=22, Supplier Device Package=0603, Supplier Part Number 1=311-22GRCT-ND, Temperature Coefficient=±100ppm/°C, Tolerance=±5%
R35 R36 R38 R39 R60 R61: "Resistor", Manufacturer=Yageo, Manufacturer Part Number=RC0603JR-075K1L, Operating Temperature="-55°C ~ 155°C", Package / Case="0603 (1608 Metric)", Power (Watts)="0.1W, 1/10W", Resistance (Ohms)=5.1k, Supplier Device Package=0603, Supplier Part Number 1=311-5.1KGRCT-ND, Temperature Coefficient=±100ppm/°C, Tolerance=±5%
R43: "Resistor", Manufacturer=Yageo, Manufacturer Part Number=RT0603BRD0739KL, Operating Temperature="-55°C ~ 155°C", Package / Case="0603 (1608 Metric)", Power (Watts)="0.1W, 1/10W", Resistance (Ohms)=39k, Supplier Device Package=0603, Supplier Part Number 1=YAG1649CT-ND, Temperature Coefficient=±25ppm/°C, Tolerance=±0.1%
R44: "Resistor", Manufacturer=Yageo, Manufacturer Part Number=AT0603BRD072KL, Operating Temperature="-55°C ~ 155°C", Package / Case="0603 (1608 Metric)", Power (Watts)="0.1W, 1/10W", Resistance (Ohms)=2k, Supplier Device Package=0603, Supplier Part Number 1=YAG2112CT-ND, Temperature Coefficient=±25ppm/°C, Tolerance=±0.1%
R47 R50 R53 R56: "Resistor", Manufacturer=Yageo, Manufacturer Part Number=RC0603FR-072RL, Operating Temperature="-55°C ~ 155°C", Package / Case="0603 (1608 Metric)", Power (Watts)="0.1W, 1/10W", Resistance (Ohms)=2, Supplier Device Package=0603, Supplier Part Number 1=311-2.00HRCT-ND, Temperature Coefficient=±200ppm/°C, Tolerance=±1%
R48 R51 R54 R57: "Resistor", Manufacturer=Yageo, Manufacturer Part Number=RC0603JR-07110KL, Operating Temperature="-55°C ~ 155°C", Package / Case="0603 (1608 Metric)", Power (Watts)="0.1W, 1/10W", Resistance (Ohms)=110k, Supplier Device Package=0603, Supplier Part Number 1=311-110KGRCT-ND, Temperature Coefficient=±100ppm/°C, Tolerance=±5%
Ref1: Current - Cathode=-, Current - Output=10mA, Current - Supply=600µA, Digikey Part Number=LT6654AHS6-3.3#TRMPBFCT-ND, Manufacturer="Linear Technology", Operating Temperature="-40°C ~ 125°C (TA)", Package / Case="SOT-23-6 Thin, TSOT-23-6", Supplier Device Package=TSOT-23-6, Temperature Coefficient=10ppm/°C, Tolerance=±0.05%, Voltage - Input="3.8 V ~ 36 V", Voltage - Output (Min/Fixed)=3.3V
REG1: Current - Output (Max)=1.5A, Manufacturer="Murata Power Solutions Inc.", Manufacturer Part Number=OKI-78SR-3.3/1.5-W36-C, Operating Temperature="-40°C ~ 85°C", Package / Case="3-SIP Module", Power (Watts) - Manufacture Series=5W, Supplier Part Number 1=811-2195-5-ND, Voltage - Input (Max)=36V, Voltage - Input (Min)=7V, Voltage - Isolation=-, Voltage - Output 1=3.3V
REG2: library part OKI-78SR-5, "3.3V DCDC", Current - Output (Max)=1.5A, Manufacturer="Murata Power Solutions Inc.", Manufacturer Part Number=OKI-78SR-3.3/1.5-W36H-C, Operating Temperature="-40°C ~ 85°C", Package / Case="3-SIP Module", Power (Watts) - Manufacture Series=5W, Supplier Part Number 1=811-2196-5-ND, Voltage - Input (Max)=36V, Voltage - Input (Min)=7V, Voltage - Isolation=-, Voltage - Output 1=3.3V
U1: library part CMP-0243-00217-1, "ARM Cortex-M4 32-bit MCU+FPU, 256 KB Flash, 128 KB Internal RAM, 50 I/Os, 64-Pin LQFP, -40 to 105 degC, Tape and Reel", I/Os (High Current)=50, Operating Frequency(F) (Processor speed) (MHz)=180, Package Description=LQFP64, Package Reference="64-Pin Low-profile Quad Flat Package, Body 10 x 10 mm, Pitch 0.5 mm", Supply Voltage(Vcc) min (V)=1.7
U2 U3: library part CMP-0315-00075-2, "3.3 V Can Transceiver, 17 mA, -40 to 85 degC, 8-pin SOIC (D), Green (RoHS & no Sb/Br)", Drivers Per Package=1, Manufacturer="Texas Instruments", Rating=Catalog, Supply Voltage(s)(V)=3.3
X1: library part "8MHz crystal, 7A-8.000MAAJ-T", ESR (Equivalent Series Resistance)="80 Ohm", Frequency=8MHz, Frequency Stability=±30ppm, Load Capacitance=18pF, Manufacturer="TXC CORPORATION", Operating Mode=Fundamental, Operating Temperature="-20°C ~ 70°C", Package / Case="2-SMD, No Lead", Ratings=-, Supplier Part Number 1=887-1448-1-ND

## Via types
v1: diameter 0.787, hole 0.432, Top Layer to Bottom Layer, 391 vias
v2: diameter 1.27, hole 0.711, Top Layer to Bottom Layer, 9 vias
v3: diameter 3.5, hole 3, Top Layer to Bottom Layer, 2 vias
v4: diameter 4, hole 3.5, Top Layer to Bottom Layer, 2 vias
